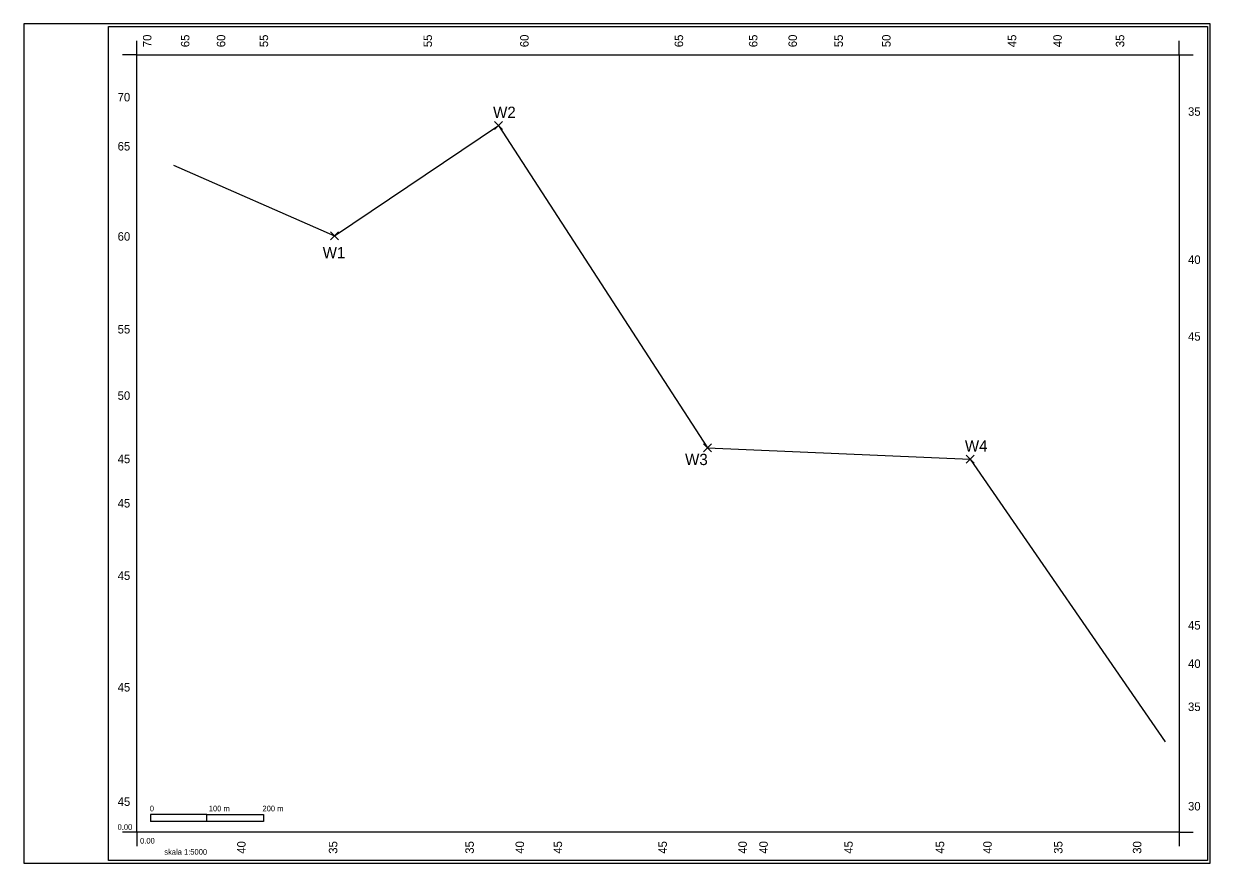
# Model space of a CAD drawing. Extents: x -200 to 1900, y -55 to 1430.
import ezdxf

# ---------------------------------------------------------------- set-up
doc = ezdxf.new("R2010")
doc.units = 0
doc.layers.add('Domyślna', color=7, linetype='Continuous')
doc.layers.add('trasa1', color=7, linetype='Continuous')

msp = doc.modelspace()

# ---------------------------------------------------------------- linework, layer by layer
at = {"layer": 'Domyślna'}
for p, q in [((0, 1375), (0, 1400)), ((1845, 1375), (1845, 1400)), ((0, 1375), (-25, 1375)), ((1845, 1375), (1870, 1375)), ((124.3, 31.4), (24.3, 31.4)), ((24.3, 31.4), (24.3, 18.9)), ((124.3, 18.9), (24.3, 18.9)), ((0, 0), (-25, 0)), ((0, 0), (0, -25)), ((1845, 0), (1845, -25)), ((1845, 0), (1870, 0))]:
    msp.add_line(p, q, dxfattribs=at)
for points in [[(-200, -55), (1900, -55), (1900, 1430), (-200, 1430)], [(-50, -50), (-50, 1425), (1895, 1425), (1895, -50)], [(0, 1375), (1845, 1375), (1845, 0), (0, 0)], [(224.3, 18.9), (124.3, 18.9), (124.3, 31.4), (224.3, 31.4)]]:
    msp.add_lwpolyline(points, close=True, dxfattribs=at)
at = {"layer": 'trasa1'}
for p, q in [((632.9, 1257.1), (647.1, 1242.9)), ((647.1, 1257.1), (632.9, 1242.9)), ((342.9, 1062.1), (357.1, 1047.9)), ((357.1, 1062.1), (342.9, 1047.9)), ((1002.9, 687.1), (1017.1, 672.9)), ((1017.1, 687.1), (1002.9, 672.9)), ((1467.9, 667.1), (1482.1, 652.9)), ((1482.1, 667.1), (1467.9, 652.9))]:
    msp.add_line(p, q, dxfattribs=at)
msp.add_lwpolyline([(65, 1180), (350, 1055), (640, 1250), (1010, 680), (1475, 660), (1820, 160)], dxfattribs=at)

# ---------------------------------------------------------------- texts
at = {"layer": 'Domyślna'}
for s, p in [('70', (26, 1388.5)), ('65', (93.2, 1388.5)), ('60', (156.7, 1388.5)), ('55', (232.5, 1388.5)), ('55', (522.6, 1388.5)), ('60', (693.6, 1388.5)), ('65', (967, 1388.5)), ('65', (1098.5, 1388.5)), ('60', (1168.4, 1388.5)), ('55', (1249.8, 1388.5)), ('50', (1334.2, 1388.5)), ('45', (1556.7, 1388.5)), ('40', (1637.2, 1388.5)), ('35', (1747.8, 1388.5)), ('40', (192.7, -38.2)), ('35', (355, -38.2)), ('35', (596.6, -38.2)), ('40', (685.4, -38.2)), ('45', (752.8, -38.2)), ('45', (938.3, -38.2)), ('40', (1079.8, -38.2)), ('40', (1116.9, -38.2)), ('45', (1267.2, -38.2)), ('45', (1429.1, -38.2)), ('40', (1513.2, -38.2)), ('35', (1638.4, -38.2)), ('30', (1778, -38.2))]:
    msp.add_text(s, height=15, rotation=90, dxfattribs=at).set_placement(p)
for s, height, p in [('70', 15, (-33.8, 1292.6)), ('35', 15, (1860.6, 1267.2)), ('65', 15, (-33.8, 1205.8)), ('60', 15, (-33.8, 1046.3)), ('40', 15, (1860.6, 1005.2)), ('55', 15, (-33.8, 882.1)), ('45', 15, (1860.6, 869.4)), ('50', 15, (-33.8, 764.8)), ('45', 15, (-33.8, 652.7)), ('45', 15, (-33.8, 574.3)), ('45', 15, (-33.8, 446.1)), ('45', 15, (1860.6, 358.4)), ('40', 15, (1860.6, 290.5)), ('45', 15, (-33.8, 248.8)), ('35', 15, (1860.6, 214.3)), ('45', 15, (-33.8, 46.4)), ('0', 10, (23.2, 36.8)), ('100 m', 10, (127.5, 36.8)), ('200 m', 10, (222.5, 36.8)), ('30', 15, (1860.6, 38.4)), ('0.00', 10, (-33.9, 4.1)), ('0.00', 10, (5.9, -20.2)), ('skala 1:5000', 10, (48.7, -39.9))]:
    msp.add_text(s, height=height, dxfattribs=at).set_placement(p)
at = {"layer": 'trasa1'}
for s, p in [('W2', (630.7, 1263.3)), ('W1', (329.1, 1015.2)), ('W4', (1465.7, 673.3)), ('W3', (970.5, 649.3))]:
    msp.add_text(s, height=20, dxfattribs=at).set_placement(p)

doc.saveas('drawing.dxf')
